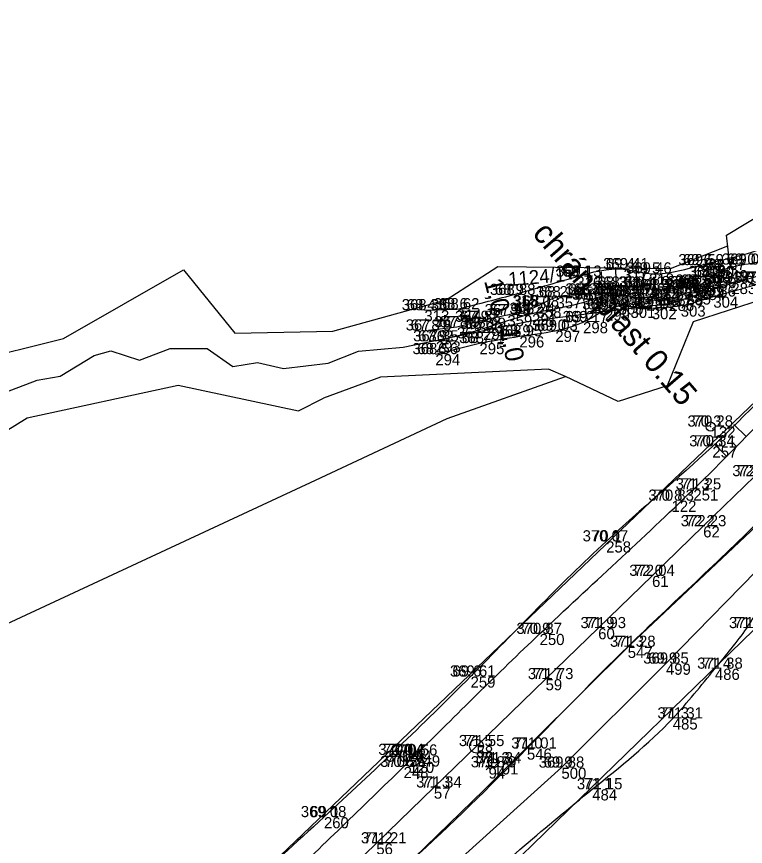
# Model space of a CAD drawing. Extents: x -514509 to -512782, y -1144610 to -1143439.
# Drawn here: x -514392.4 to -514313.9, y -1144430.3 to -1144341 of the extents above; entities that cross this region are included whole.
import ezdxf

# ---------------------------------------------------------------- set-up
doc = ezdxf.new("R2010")
doc.units = 0
for name, color, linetype in [('Vrstva 1', 7, 'Continuous'), ('Vrstva 10', 7, 'Continuous'), ('Vrstva 11', 7, 'Continuous'), ('Vrstva 12', 7, 'Continuous'), ('Vrstva 14', 7, 'Continuous'), ('Vrstva 57', 7, 'Continuous'), ('Vrstva 58', 7, 'Continuous'), ('Vrstva 59', 7, 'Continuous'), ('Vrstva 6', 7, 'Continuous'), ('Vrstva 60', 7, 'Continuous'), ('Vrstva 62', 7, 'Continuous'), ('Vrstva 8', 7, 'Continuous'), ('Vrstva 9', 7, 'Continuous')]:
    doc.layers.add(name, color=color, linetype=linetype)

msp = doc.modelspace()

# ---------------------------------------------------------------- linework, layer by layer
at = {"layer": 'Vrstva 1'}
msp.add_lwpolyline([(-514458.154, -1144538.146), (-514438.738, -1144518.384), (-514427.594, -1144508.571), (-514426.453, -1144506.765), (-514425.552, -1144504.497), (-514424.424, -1144503.017), (-514415.468, -1144494.728), (-514412.453, -1144491.947), (-514409.611, -1144489.438), (-514398.599, -1144478.624), (-514395.108, -1144475.147), (-514387.71, -1144468.188), (-514375.731, -1144457.039), (-514362.166, -1144443.724), (-514342.054, -1144424.225), (-514326.327, -1144408.585), (-514312.133, -1144395.198), (-514306.678, -1144390.3), (-514298.862, -1144383.357), (-514285.783, -1144371.722), (-514278.823, -1144367.292), (-514270.113, -1144359.369), (-514262.317, -1144351.754), (-514245.854, -1144335.108)], dxfattribs=at)
at = {"layer": 'Vrstva 10'}
msp.add_line((-514317.718, -1144385.104), (-514317.618, -1144385.104), dxfattribs=at)
msp.add_line((-514317.718, -1144385.104), (-514317.618, -1144385.104), dxfattribs=at)
msp.add_line((-514317.718, -1144385.104), (-514317.618, -1144385.104), dxfattribs=at)
msp.add_line((-514317.718, -1144385.104), (-514317.618, -1144385.104), dxfattribs=at)
for points in [[(-514499.819, -1144558.314), (-514478.557, -1144543.138), (-514461.519, -1144527.903), (-514460.881, -1144522.921), (-514467.806, -1144507.951), (-514463.437, -1144504.318), (-514455.636, -1144521.761), (-514416.221, -1144483.68), (-514393.167, -1144461.734), (-514369.711, -1144436.746), (-514306.194, -1144376.041), (-514315.59, -1144367.645), (-514315.978, -1144364.474), (-514264.396, -1144333.352), (-514260.011, -1144328.496), (-514252.731, -1144315.601), (-514243.166, -1144315.871), (-514219.401, -1144293.726)], [(-514200.74, -1144295.636), (-514262.452, -1144355.017), (-514268.983, -1144370.755), (-514278.697, -1144366.838), (-514289.275, -1144383.939), (-514344.28, -1144437.349), (-514361.723, -1144450.643), (-514428.349, -1144510.282), (-514450.694, -1144530.929), (-514439.937, -1144548.904), (-514445.489, -1144551.626), (-514469.812, -1144568.673), (-514482.71, -1144578.196)], [(-514200.74, -1144295.636), (-514262.452, -1144355.017), (-514268.983, -1144370.755), (-514278.697, -1144366.838), (-514289.275, -1144383.939), (-514344.28, -1144437.349), (-514361.723, -1144450.643), (-514428.349, -1144510.282), (-514450.694, -1144530.929), (-514439.937, -1144548.904), (-514445.489, -1144551.626), (-514469.812, -1144568.673), (-514482.71, -1144578.196)], [(-514327.919, -1144368.228), (-514327.852, -1144370.122)], [(-514326.499, -1144368.181), (-514326.465, -1144368.935)], [(-514330.929, -1144368.698), (-514330.861, -1144370.811)], [(-514329.475, -1144368.432), (-514329.44, -1144369.201)], [(-514324.943, -1144368.557), (-514324.893, -1144370.168)], [(-514358.85, -1144378.276), (-514355.601, -1144376.98), (-514350.775, -1144376.555), (-514337.028, -1144373.705), (-514321.886, -1144371.798), (-514313.941, -1144369.193)], [(-514328.107, -1144371.997), (-514328.326, -1144370.819)], [(-514330.93, -1144373.542), (-514331.28, -1144371.642)], [(-514326.577, -1144372.107), (-514326.616, -1144371.629)], [(-514325.026, -1144372.31), (-514325.165, -1144371.316)], [(-514348.5, -1144372.573), (-514345.006, -1144372.468)], [(-514329.539, -1144372.751), (-514329.689, -1144372.013)], [(-514342.763, -1144373.818), (-514345.005, -1144374.395), (-514348.068, -1144374.75)], [(-514347.319, -1144377.302), (-514342.567, -1144376.113)], [(-514393.685, -1144381.437), (-514390.224, -1144380.101), (-514387.736, -1144379.686), (-514384.086, -1144377.431), (-514382.288, -1144376.941), (-514379.174, -1144377.959), (-514375.894, -1144376.689), (-514371.883, -1144376.693), (-514369.129, -1144378.612), (-514366.469, -1144378.215), (-514363.662, -1144378.859), (-514358.85, -1144378.276)], [(-514290.188, -1144383.67), (-514289.896, -1144381.564), (-514296.329, -1144386.021), (-514304.22, -1144392.44), (-514311.112, -1144398.986), (-514322.482, -1144410.619), (-514333.737, -1144421.82), (-514348.453, -1144435.067), (-514360.873, -1144445.147), (-514371.608, -1144455.186)], [(-514313.855, -1144386.159), (-514315.156, -1144384.865)], [(-514315.972, -1144388.286), (-514317.258, -1144387.006)], [(-514314.914, -1144387.223), (-514315.431, -1144386.708)], [(-514349.485, -1144420.51), (-514350.741, -1144421.741)]]:
    msp.add_lwpolyline(points, dxfattribs=at)
msp.add_circle((-514317.668, -1144385.104), 0.5, dxfattribs=at)
msp.add_circle((-514317.668, -1144385.104), 0.5, dxfattribs=at)
msp.add_circle((-514317.668, -1144385.104), 0.5, dxfattribs=at)
msp.add_circle((-514317.668, -1144385.104), 0.5, dxfattribs=at)
for points in [[(-514345.006, -1144372.468), (-514339, -1144370.919), (-514332.132, -1144368.96), (-514327.047, -1144368.152), (-514324.3, -1144368.614), (-514318.701, -1144367.716), (-514310.86, -1144365.398), (-514307.1, -1144363.156), (-514303.155, -1144360.871), (-514298.049, -1144359.104), (-514294.093, -1144356.358), (-514291.416, -1144353.875), (-514289.198, -1144352.116), (-514287.282, -1144351.664), (-514285.28, -1144351.581), (-514283.438, -1144351.88)], [(-514282.881, -1144354.839), (-514284.701, -1144354.946), (-514286.114, -1144355.206), (-514287.467, -1144355.764), (-514289.095, -1144356.547), (-514291.298, -1144357.752), (-514294.622, -1144359.56), (-514296.268, -1144360.296), (-514299.955, -1144361.854), (-514302.721, -1144362.565), (-514305.106, -1144363.504), (-514307.211, -1144364.859), (-514308.701, -1144366.178), (-514311.169, -1144367.109), (-514313.97, -1144367.659), (-514316.343, -1144368.246), (-514317.568, -1144368.996), (-514318.98, -1144369.924), (-514320.496, -1144370.09), (-514323.355, -1144370.42), (-514325.041, -1144370.142), (-514327.938, -1144370.126), (-514331.135, -1144370.868), (-514334.271, -1144371.171), (-514336.416, -1144372.179), (-514339.557, -1144373.1), (-514342.763, -1144373.818)], [(-514284.056, -1144355.864), (-514285.718, -1144355.857), (-514287.215, -1144356.176), (-514290.495, -1144357.82), (-514297.573, -1144362.027), (-514302.712, -1144364.128), (-514304.792, -1144364.535), (-514306.458, -1144365.602), (-514308.375, -1144367.098), (-514311.124, -1144368.417), (-514315.439, -1144369.627), (-514318.802, -1144370.285), (-514320.321, -1144370.759), (-514322.123, -1144371.435), (-514324.605, -1144371.421), (-514326.552, -1144371.055), (-514328.232, -1144370.828), (-514330.421, -1144371.438), (-514336.896, -1144372.952), (-514342.168, -1144374.567), (-514347.273, -1144375.919)], [(-514342.567, -1144376.113), (-514338.27, -1144375.378), (-514334.402, -1144374.782), (-514331.412, -1144373.852), (-514329.046, -1144372.478), (-514327.579, -1144371.836), (-514326.3, -1144372.204), (-514324.011, -1144372.345), (-514320.893, -1144372.062), (-514317.377, -1144371.105), (-514312.223, -1144369.601), (-514308.126, -1144367.819), (-514304.782, -1144365.924)], [(-514376.183, -1144455.825), (-514364.057, -1144444.171), (-514349.904, -1144431.834), (-514337.456, -1144419.763), (-514326.602, -1144408.809), (-514311.923, -1144394.732), (-514302.743, -1144385.771), (-514299.077, -1144382.829), (-514289.887, -1144376.167)], [(-514306.829, -1144376.492), (-514317.483, -1144387.235), (-514328.923, -1144397.462), (-514343.53, -1144412.007), (-514359.325, -1144427.154), (-514377.218, -1144443.639), (-514396.999, -1144463.938), (-514416.449, -1144483.281), (-514432.576, -1144498.996), (-514444.812, -1144511.83)], [(-514349.485, -1144420.51), (-514336.089, -1144407.419), (-514319.528, -1144391.859), (-514310.45, -1144382.737)], [(-514368.878, -1144458.719), (-514357.635, -1144448.781), (-514344.876, -1144436.577), (-514330.422, -1144424.152), (-514321.75, -1144416.523), (-514317.211, -1144411.172), (-514313.786, -1144406.796), (-514310.617, -1144401.889), (-514304.463, -1144395.826), (-514299.086, -1144391.199), (-514295.236, -1144389.016), (-514292.221, -1144387.032), (-514290.786, -1144385.359), (-514290.188, -1144383.67)], [(-514378.517, -1144448.432), (-514364.053, -1144434.598), (-514350.741, -1144421.741)]]:
    msp.add_spline(points, degree=3, dxfattribs=at)
at = {"layer": 'Vrstva 12'}
for p, q in [((-514341.341, -1144421.546), (-514341.838, -1144422.039)), ((-514341.343, -1144422.041), (-514341.836, -1144421.544))]:
    msp.add_line(p, q, dxfattribs=at)
at = {"layer": 'Vrstva 14'}
msp.add_circle((-514341.063, -1144421.351), 0.5, dxfattribs=at)
at = {"layer": 'Vrstva 6'}
msp.add_lwpolyline([(-514395.915, -1144470.927), (-514389.978, -1144465.169), (-514383.411, -1144458.801), (-514378.819, -1144454.348), (-514372.321, -1144448.047), (-514365.819, -1144441.742), (-514360.062, -1144436.158), (-514353.679, -1144429.968), (-514347.481, -1144423.958), (-514342.883, -1144419.499), (-514335.447, -1144412.288), (-514329.785, -1144406.797), (-514323.983, -1144401.171), (-514318.472, -1144395.826), (-514312.921, -1144390.444), (-514308.072, -1144385.742), (-514302.67, -1144380.503), (-514295.811, -1144373.851), (-514289.957, -1144368.174), (-514283.087, -1144361.513), (-514276.536, -1144355.159), (-514270.172, -1144348.988), (-514263.322, -1144342.345), (-514259.456, -1144338.596)], dxfattribs=at)
msp.add_circle((-514342.883, -1144419.499), 0.75, dxfattribs=at)
at = {"layer": 'Vrstva 60'}
for p, q in [((-514327.05, -1144368.15), (-514327.05, -1144368.15)), ((-514318.7, -1144367.72), (-514318.7, -1144367.72)), ((-514316.34, -1144368.25), (-514316.34, -1144368.25)), ((-514313.97, -1144367.66), (-514313.97, -1144367.66)), ((-514332.13, -1144368.96), (-514332.13, -1144368.96)), ((-514324.3, -1144368.61), (-514324.3, -1144368.61)), ((-514317.57, -1144369), (-514317.57, -1144369)), ((-514318.98, -1144369.92), (-514318.98, -1144369.92)), ((-514315.44, -1144369.63), (-514315.44, -1144369.63)), ((-514339, -1144370.92), (-514339, -1144370.92)), ((-514331.13, -1144370.87), (-514331.13, -1144370.87)), ((-514328.23, -1144370.83), (-514328.23, -1144370.83)), ((-514327.94, -1144370.13), (-514327.94, -1144370.13)), ((-514325.04, -1144370.14), (-514325.04, -1144370.14)), ((-514323.35, -1144370.42), (-514323.35, -1144370.42)), ((-514320.5, -1144370.09), (-514320.5, -1144370.09)), ((-514320.32, -1144370.76), (-514320.32, -1144370.76)), ((-514318.8, -1144370.28), (-514318.8, -1144370.28)), ((-514334.27, -1144371.17), (-514334.27, -1144371.17)), ((-514330.42, -1144371.44), (-514330.42, -1144371.44)), ((-514327.58, -1144371.84), (-514327.58, -1144371.84)), ((-514326.55, -1144371.06), (-514326.55, -1144371.06)), ((-514324.6, -1144371.42), (-514324.6, -1144371.42)), ((-514322.12, -1144371.44), (-514322.12, -1144371.44)), ((-514317.38, -1144371.1), (-514317.38, -1144371.1)), ((-514348.5, -1144372.57), (-514348.5, -1144372.57)), ((-514345.01, -1144372.47), (-514345.01, -1144372.47)), ((-514336.42, -1144372.18), (-514336.42, -1144372.18)), ((-514329.05, -1144372.48), (-514329.05, -1144372.48)), ((-514326.3, -1144372.2), (-514326.3, -1144372.2)), ((-514324.01, -1144372.34), (-514324.01, -1144372.34)), ((-514320.89, -1144372.06), (-514320.89, -1144372.06)), ((-514339.56, -1144373.1), (-514339.56, -1144373.1)), ((-514336.9, -1144372.95), (-514336.9, -1144372.95)), ((-514345, -1144374.4), (-514345, -1144374.4)), ((-514342.76, -1144373.82), (-514342.76, -1144373.82)), ((-514331.41, -1144373.85), (-514331.41, -1144373.85)), ((-514348.07, -1144374.75), (-514348.07, -1144374.75)), ((-514342.17, -1144374.57), (-514342.17, -1144374.57)), ((-514338.27, -1144375.38), (-514338.27, -1144375.38)), ((-514334.4, -1144374.78), (-514334.4, -1144374.78)), ((-514347.27, -1144375.92), (-514347.27, -1144375.92)), ((-514342.57, -1144376.11), (-514342.57, -1144376.11)), ((-514347.32, -1144377.3), (-514347.32, -1144377.3)), ((-514317.67, -1144385.1), (-514317.67, -1144385.1)), ((-514317.48, -1144387.23), (-514317.48, -1144387.23)), ((-514319.53, -1144391.86), (-514319.53, -1144391.86)), ((-514321.88, -1144393.08), (-514321.88, -1144393.08)), ((-514318.47, -1144395.83), (-514318.47, -1144395.83)), ((-514328.92, -1144397.46), (-514328.92, -1144397.46)), ((-514323.98, -1144401.17), (-514323.98, -1144401.17)), ((-514336.09, -1144407.42), (-514336.09, -1144407.42)), ((-514329.78, -1144406.8), (-514329.78, -1144406.8)), ((-514326.6, -1144408.81), (-514326.6, -1144408.81)), ((-514322.48, -1144410.62), (-514322.48, -1144410.62)), ((-514343.53, -1144412.01), (-514343.53, -1144412.01)), ((-514317.21, -1144411.17), (-514317.21, -1144411.17)), ((-514335.45, -1144412.29), (-514335.45, -1144412.29)), ((-514321.75, -1144416.52), (-514321.75, -1144416.52)), ((-514342.88, -1144419.5), (-514342.88, -1144419.5)), ((-514337.46, -1144419.76), (-514337.46, -1144419.76)), ((-514350.93, -1144420.45), (-514350.93, -1144420.45)), ((-514349.49, -1144420.51), (-514349.49, -1144420.51)), ((-514350.74, -1144421.74), (-514350.74, -1144421.74)), ((-514350.13, -1144421.19), (-514350.13, -1144421.19)), ((-514341.59, -1144421.79), (-514341.59, -1144421.79)), ((-514341.06, -1144421.35), (-514341.06, -1144421.35)), ((-514333.74, -1144421.82), (-514333.74, -1144421.82)), ((-514347.48, -1144423.96), (-514347.48, -1144423.96)), ((-514330.42, -1144424.15), (-514330.42, -1144424.15)), ((-514359.32, -1144427.15), (-514359.32, -1144427.15)), ((-514353.68, -1144429.97), (-514353.68, -1144429.97))]:
    msp.add_line(p, q, dxfattribs=at)
at = {"layer": 'Vrstva 8'}
for points in [[(-514358.369, -1144374.843), (-514346.141, -1144371.465), (-514340.597, -1144367.877), (-514321.988, -1144368.071), (-514315.834, -1144365.625)], [(-514493.235, -1144419.068), (-514492.005, -1144420.567), (-514472.965, -1144411.598), (-514467.284, -1144418.614), (-514458.018, -1144418.415), (-514451.287, -1144415.893), (-514423.883, -1144397.49), (-514426.758, -1144393.509), (-514397.506, -1144378.122), (-514387.376, -1144375.625), (-514374.439, -1144368.22), (-514368.911, -1144375.049), (-514358.369, -1144374.843)], [(-514312.013, -1144371.385), (-514319.543, -1144373.821), (-514322.337, -1144380.729), (-514327.622, -1144382.391), (-514333.301, -1144379.714), (-514335.144, -1144378.909), (-514353.239, -1144379.766), (-514359.362, -1144382.046)], [(-514360.238, -1144390.862), (-514346.066, -1144384.238), (-514333.301, -1144379.714)], [(-514453.473, -1144429.408), (-514446.094, -1144425.761), (-514429.597, -1144412.163), (-514415.799, -1144407.241), (-514412.434, -1144397.27), (-514391.282, -1144384.172), (-514375.02, -1144380.626), (-514362.068, -1144383.386), (-514359.362, -1144382.046)], [(-514463.437, -1144504.318), (-514480.563, -1144470.306), (-514497.456, -1144428.094), (-514498.292, -1144426.979), (-514470.886, -1144423.607), (-514456.211, -1144423.391), (-514453.473, -1144429.408), (-514451.736, -1144433.438), (-514360.238, -1144390.862)]]:
    msp.add_lwpolyline(points, dxfattribs=at)

# ---------------------------------------------------------------- texts
at = {"layer": 'Vrstva 11'}
for rotation, p in [(284.45959, (-514342.083, -1144369.416)), (281.03936, (-514340.374, -1144374.585))]:
    msp.add_text('1,0', height=2, rotation=rotation, dxfattribs=at).set_placement(p)
at = {"layer": 'Vrstva 57'}
for s, p in [('69 0 ', (-514315.95, -1144367.66)), ('69 4 ', (-514328.964, -1144368.15)), ('69 6 ', (-514320.656, -1144367.72)), ('68 7 ', (-514318.248, -1144368.25)), ('69 1 ', (-514333.62, -1144368.96)), ('69 5 ', (-514326.214, -1144368.61)), ('68 5 ', (-514319.478, -1144369)), ('68 3 ', (-514329.848, -1144370.13)), ('68 4 ', (-514326.948, -1144370.14)), ('68 5 ', (-514322.408, -1144370.09)), ('68 5 ', (-514320.888, -1144369.92)), ('68 8 ', (-514320.708, -1144370.28)), ('69 5 ', (-514317.354, -1144369.63)), ('70 2 ', (-514314.18, -1144369.6)), ('68 9 ', (-514340.913, -1144370.92)), ('68 2 ', (-514336.178, -1144371.17)), ('68 2 ', (-514333.038, -1144370.87)), ('68 4 ', (-514330.138, -1144370.83)), ('68 5 ', (-514328.458, -1144371.06)), ('68 5 ', (-514325.258, -1144370.42)), ('68 6 ', (-514322.268, -1144370.76)), ('69 9 ', (-514319.3, -1144371.1)), ('68 3 ', (-514332.328, -1144371.44)), ('69 3 ', (-514329.494, -1144371.84)), ('68 4 ', (-514326.508, -1144371.42)), ('68 5 ', (-514324.028, -1144371.44)), ('69 7 ', (-514322.804, -1144372.06)), ('68 4 ', (-514350.408, -1144372.57)), ('68 6 ', (-514346.958, -1144372.47)), ('68 2 ', (-514338.808, -1144372.95)), ('68 1 ', (-514337.902, -1144372.18)), ('69 3 ', (-514330.964, -1144372.48)), ('69 4 ', (-514328.214, -1144372.2)), ('69 5 ', (-514325.924, -1144372.34)), ('67 9 ', (-514344.673, -1144373.82)), ('67 9 ', (-514341.473, -1144373.1)), ('69 2 ', (-514333.324, -1144373.85)), ('67 8 ', (-514349.978, -1144374.75)), ('67 8 ', (-514346.908, -1144374.4)), ('68 0 ', (-514344.142, -1144374.57)), ('69 0 ', (-514336.38, -1144374.78)), ('68 9 ', (-514340.183, -1144375.38)), ('67 9 ', (-514349.183, -1144375.92)), ('68 7 ', (-514344.478, -1144376.11)), ('68 6 ', (-514349.268, -1144377.3)), ('70 3 ', (-514319.63, -1144385.1)), ('70 3 ', (-514319.44, -1144387.23)), ('72 3 ', (-514314.803, -1144390.44)), ('71 3 ', (-514320.903, -1144391.86)), ('70 8 ', (-514323.84, -1144393.08)), ('72 2 ', (-514320.353, -1144395.83)), ('70 1 ', (-514330.456, -1144397.46)), ('72 0 ', (-514325.928, -1144401.17)), ('71 9 ', (-514331.158, -1144406.8)), ('71 4 ', (-514315.163, -1144406.8)), ('70 9 ', (-514338.056, -1144407.42)), ('71 3 ', (-514327.973, -1144408.81)), ('69 9 ', (-514324.4, -1144410.62)), ('71 4 ', (-514318.583, -1144411.17)), ('69 6 ', (-514345.486, -1144412.01)), ('71 7 ', (-514336.823, -1144412.29)), ('71 3 ', (-514323.123, -1144416.52)), ('71 5 ', (-514344.253, -1144419.5)), ('71 0 ', (-514338.898, -1144419.76)), ('70 0 ', (-514352.956, -1144420.45)), ('70 4 ', (-514352.09, -1144421.19)), ('70 6 ', (-514351.492, -1144420.51)), ('70 6 ', (-514352.742, -1144421.74)), ('71 8 ', (-514342.963, -1144421.79)), ('71 3 ', (-514342.433, -1144421.35)), ('69 9 ', (-514335.66, -1144421.82)), ('71 3 ', (-514348.853, -1144423.96)), ('71 1 ', (-514331.368, -1144424.15)), ('69 1 ', (-514360.81, -1144427.15)), ('71 2 ', (-514355.053, -1144429.97))]:
    msp.add_text(s, height=1.2, dxfattribs=at).set_placement(p)
at = {"layer": 'Vrstva 58'}
for s, p in [('369 04', (-514316.462, -1144367.66)), ('369 41', (-514329.248, -1144368.15)), ('369 59', (-514321.156, -1144367.72)), ('368 67', (-514318.81, -1144368.25)), ('369 13', (-514334.328, -1144368.96)), ('369 46', (-514326.778, -1144368.61)), ('368 50', (-514320.054, -1144369)), ('368 31', (-514330.13, -1144370.13)), ('368 42', (-514327.486, -1144370.14)), ('368 52', (-514322.946, -1144370.09)), ('368 50', (-514321.464, -1144369.92)), ('368 84', (-514321.246, -1144370.28)), ('369 46', (-514317.918, -1144369.63)), ('370 16', (-514314.488, -1144369.6)), ('368 88', (-514341.446, -1144370.92)), ('368 16', (-514336.486, -1144371.17)), ('368 18', (-514333.32, -1144370.87)), ('368 41', (-514330.42, -1144370.83)), ('368 47', (-514328.996, -1144371.06)), ('368 53', (-514325.796, -1144370.42)), ('368 62', (-514322.79, -1144370.76)), ('369 86', (-514319.858, -1144371.1)), ('368 31', (-514332.61, -1144371.44)), ('369 33', (-514330.032, -1144371.84)), ('368 44', (-514327.046, -1144371.42)), ('368 52', (-514324.566, -1144371.44)), ('369 68', (-514323.368, -1144372.06)), ('368 38', (-514350.946, -1144372.57)), ('368 62', (-514347.48, -1144372.47)), ('368 24', (-514339.346, -1144372.95)), ('368 08', (-514338.904, -1144372.18)), ('369 28', (-514331.502, -1144372.48)), ('369 40', (-514328.792, -1144372.2)), ('369 48', (-514326.462, -1144372.34)), ('367 88', (-514345.206, -1144373.82)), ('367 93', (-514342.009, -1144373.1)), ('369 17', (-514333.608, -1144373.85)), ('367 78', (-514350.516, -1144374.75)), ('367 79', (-514347.449, -1144374.4)), ('367 99', (-514344.622, -1144374.57)), ('369 03', (-514336.892, -1144374.78)), ('368 95', (-514340.719, -1144375.38)), ('367 85', (-514349.716, -1144375.92)), ('368 71', (-514344.76, -1144376.11)), ('368 56', (-514349.79, -1144377.3)), ('370 28', (-514320.168, -1144385.1)), ('370 34', (-514319.978, -1144387.23)), ('372 25', (-514315.341, -1144390.44)), ('371 25', (-514321.441, -1144391.86)), ('370 83', (-514324.378, -1144393.08)), ('372 23', (-514320.891, -1144395.83)), ('370 07', (-514331.458, -1144397.46)), ('372 04', (-514326.44, -1144401.17)), ('371 93', (-514331.694, -1144406.8)), ('371 35', (-514315.701, -1144406.8)), ('370 87', (-514338.588, -1144407.42)), ('371 28', (-514328.511, -1144408.81)), ('369 85', (-514324.932, -1144410.62)), ('371 38', (-514319.121, -1144411.17)), ('369 61', (-514345.752, -1144412.01)), ('371 73', (-514337.361, -1144412.29)), ('371 31', (-514323.406, -1144416.52)), ('371 55', (-514344.791, -1144419.5)), ('371 01', (-514339.155, -1144419.76)), ('370 04', (-514353.468, -1144420.45)), ('370 44', (-514352.628, -1144421.19)), ('370 56', (-514352.014, -1144420.51)), ('370 56', (-514353.264, -1144421.74)), ('371 79', (-514343.504, -1144421.79)), ('371 34', (-514342.971, -1144421.35)), ('369 88', (-514336.192, -1144421.82)), ('371 34', (-514349.391, -1144423.96)), ('371 15', (-514332.076, -1144424.15)), ('369 08', (-514361.812, -1144427.15)), ('371 21', (-514355.336, -1144429.97))]:
    msp.add_text(s, height=1.2, dxfattribs=at).set_placement(p)
at = {"layer": 'Vrstva 59'}
for s, p in [('317', (-514327.05, -1144369.35)), ('319', (-514318.7, -1144368.92)), ('349', (-514316.34, -1144369.45)), ('316', (-514332.13, -1144370.16)), ('318', (-514324.3, -1144369.81)), ('350', (-514317.57, -1144370.2)), ('351', (-514318.98, -1144371.12)), ('283', (-514315.44, -1144370.83)), ('315', (-514339, -1144372.12)), ('356', (-514331.13, -1144372.07)), ('289', (-514328.23, -1144372.03)), ('355', (-514327.94, -1144371.33)), ('354', (-514325.04, -1144371.34)), ('353', (-514323.35, -1144371.62)), ('352', (-514320.5, -1144371.29)), ('285', (-514320.32, -1144371.96)), ('284', (-514318.8, -1144371.48)), ('357', (-514334.27, -1144372.37)), ('290', (-514330.42, -1144372.64)), ('300', (-514327.58, -1144373.04)), ('288', (-514326.55, -1144372.26)), ('287', (-514324.6, -1144372.62)), ('286', (-514322.12, -1144372.64)), ('304', (-514317.38, -1144372.3)), ('313', (-514348.5, -1144373.77)), ('314', (-514345.01, -1144373.67)), ('358', (-514336.42, -1144373.38)), ('299', (-514329.05, -1144373.68)), ('301', (-514326.3, -1144373.4)), ('302', (-514324.01, -1144373.54)), ('303', (-514320.89, -1144373.26)), ('359', (-514339.56, -1144374.3)), ('291', (-514336.9, -1144374.15)), ('361', (-514345, -1144375.6)), ('360', (-514342.76, -1144375.02)), ('298', (-514331.41, -1144375.05)), ('362', (-514348.07, -1144375.95)), ('292', (-514342.17, -1144375.77)), ('296', (-514338.27, -1144376.58)), ('297', (-514334.4, -1144375.98)), ('293', (-514347.27, -1144377.12)), ('295', (-514342.57, -1144377.31)), ('294', (-514347.32, -1144378.5)), ('132', (-514317.67, -1144386.3)), ('257', (-514317.48, -1144388.43)), ('251', (-514319.53, -1144393.06)), ('122', (-514321.88, -1144394.28)), ('62', (-514318.47, -1144397.03)), ('258', (-514328.92, -1144398.66)), ('61', (-514323.98, -1144402.37)), ('250', (-514336.09, -1144408.62)), ('60', (-514329.78, -1144408)), ('547', (-514326.6, -1144410.01)), ('499', (-514322.48, -1144411.82)), ('486', (-514317.21, -1144412.37)), ('259', (-514343.53, -1144413.21)), ('59', (-514335.45, -1144413.49)), ('485', (-514321.75, -1144417.72)), ('58', (-514342.88, -1144420.7)), ('546', (-514337.46, -1144420.96)), ('121', (-514350.93, -1144421.65)), ('249', (-514349.49, -1144421.71)), ('248', (-514350.74, -1144422.94)), ('120', (-514350.13, -1144422.39)), ('94', (-514341.59, -1144422.99)), ('101', (-514341.06, -1144422.55)), ('500', (-514333.74, -1144423.02)), ('57', (-514347.48, -1144425.16)), ('484', (-514330.42, -1144425.35)), ('260', (-514359.32, -1144428.35)), ('56', (-514353.68, -1144431.17))]:
    msp.add_text(s, height=1.2, dxfattribs=at).set_placement(p)
at = {"layer": 'Vrstva 62'}
msp.add_text('chrán. plast 0.15', height=2.5, rotation=310.84718, dxfattribs=at).set_placement((-514336.97, -1144364.376))
at = {"layer": 'Vrstva 9'}
msp.add_text('1124/1', height=1.5, rotation=4.95186, dxfattribs=at).set_placement((-514339.405, -1144369.989))

doc.saveas('drawing.dxf')
